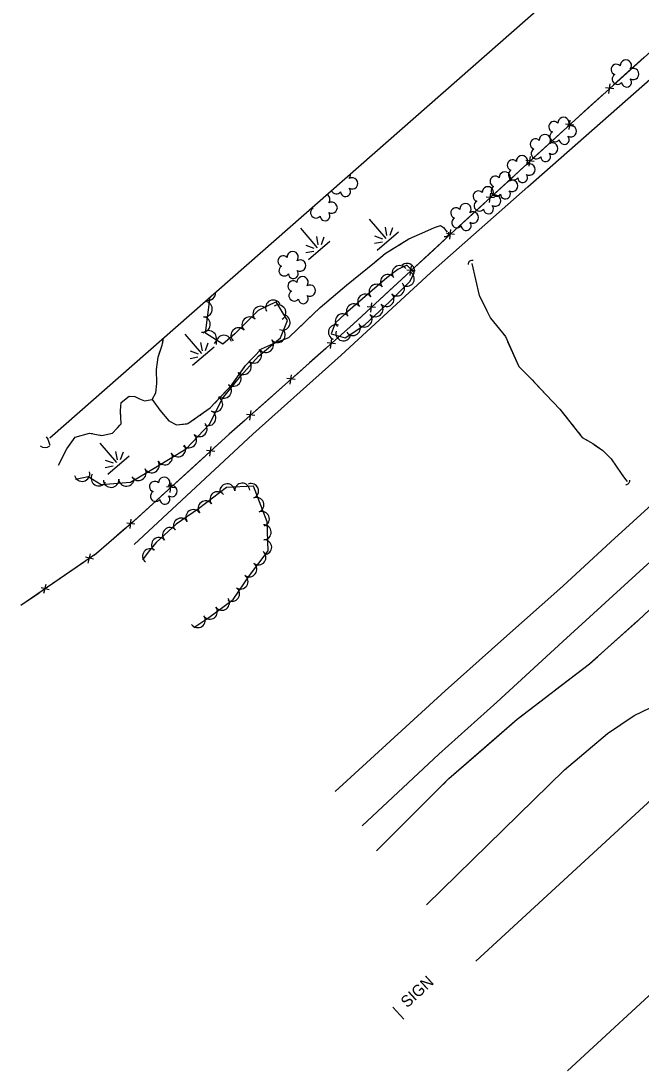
# Model space of a CAD drawing. Extents: x 295302 to 297577, y 27143 to 29590.
# Drawn here: x 295710 to 296036, y 28030 to 28582 of the extents above; entities that cross this region are included whole.
import ezdxf

# ---------------------------------------------------------------- set-up
doc = ezdxf.new("R2010")
doc.units = 0
for name, color, linetype in [('Level 11', 7, 'Continuous'), ('Level 12', 7, 'Continuous'), ('Level 14', 7, 'Continuous'), ('Level 15', 7, 'Continuous'), ('Level 17', 7, 'Continuous'), ('Level 18', 7, 'Continuous'), ('Level 19', 7, 'Continuous'), ('Level 4', 7, 'Continuous')]:
    doc.layers.add(name, color=color, linetype=linetype)

msp = doc.modelspace()

# ---------------------------------------------------------------- linework, layer by layer
at = {"layer": 'Level 11'}
for points in [[(295875.36, 28176.97), (295933.16, 28229.89), (295963.95, 28257.42), (295994.85, 28284.91), (296020.17, 28308.14), (296053.31, 28338.3), (296080.66, 28364.03), (296109.33, 28390.19), (296137.45, 28415.82), (296168.64, 28444.28), (296193.89, 28466.94), (296211.46, 28483.1), (296243.37, 28511.75), (296271.82, 28538.33), (296291, 28555.78), (296294.87, 28559.97), (296297.65, 28563.85)], [(295889.55, 28159.05), (295929.9, 28196.61), (295960.23, 28223.99), (295994.84, 28255.85), (296037.19, 28294.52), (296061.88, 28316.46), (296091.53, 28343.54), (296125.49, 28375.06), (296156.05, 28402.79), (296185.39, 28429.34), (296231.09, 28471.28), (296271.66, 28507.98), (296280.16, 28516.21), (296284, 28519.76), (296286.47, 28521.53), (296289.27, 28523.36), (296290.75, 28524.15), (296293.46, 28524.51), (296295.97, 28523.95)]]:
    msp.add_lwpolyline(points, dxfattribs=at)
at = {"layer": 'Level 12'}
msp.add_lwpolyline([(295997.3, 28030.32), (296109.73, 28134.03), (296059.4, 28189.22), (295949.16, 28088.06)], dxfattribs=at)
at = {"layer": 'Level 14'}
msp.add_line((295905.59, 28063.79), (295911.52, 28057.47), dxfattribs=at)
at = {"layer": 'Level 15'}
for p, q in [((296019.55, 28548.5), (296018.96, 28543.53)), ((296021.63, 28545.95), (296017.36, 28546.43)), ((296000.67, 28526.93), (295996.4, 28527.38)), ((295998.57, 28529.47), (295998.02, 28524.49)), ((295977.72, 28510.33), (295977.16, 28505.35)), ((295979.82, 28507.78), (295975.54, 28508.24)), ((295958.96, 28488.64), (295954.69, 28489.09)), ((295956.86, 28491.18), (295956.31, 28486.2)), ((295936.01, 28472.03), (295935.47, 28467.05)), ((295938.12, 28469.49), (295933.84, 28469.93)), ((295917.32, 28450.29), (295913.04, 28450.73)), ((295915.21, 28452.82), (295914.67, 28447.84)), ((295896.52, 28431.08), (295892.24, 28431.52)), ((295894.41, 28433.62), (295893.87, 28428.64)), ((295875.52, 28412.05), (295871.26, 28412.58)), ((295873.46, 28414.63), (295872.82, 28409.66)), ((295854.35, 28393.25), (295850.09, 28393.78)), ((295852.3, 28395.83), (295851.66, 28390.86)), ((295831.13, 28377.03), (295830.49, 28372.06)), ((295833.19, 28374.45), (295828.92, 28374.97)), ((295812.13, 28355.56), (295807.86, 28356.03)), ((295810.04, 28358.11), (295809.47, 28353.13)), ((295789.11, 28339.05), (295788.53, 28334.08)), ((295791.19, 28336.5), (295786.92, 28336.97)), ((295770.23, 28317.43), (295765.97, 28317.99)), ((295768.19, 28320.03), (295767.51, 28315.06)), ((295748.55, 28298.98), (295744.39, 28300.03)), ((295746.83, 28301.79), (295745.58, 28296.94)), ((295725.2, 28282.98), (295721.03, 28284.03)), ((295723.48, 28285.79), (295722.22, 28280.94))]:
    msp.add_line(p, q, dxfattribs=at)
for points in [[(296276.18, 28846.07), (296285.34, 28791.28), (296208.62, 28719.5), (296139.52, 28656.15), (296075.6, 28596.91), (296001.45, 28529.71), (295938.47, 28471.89), (295884.83, 28422.36), (295819.8, 28364.6), (295769.53, 28318.85), (295750.14, 28301.92), (295710.44, 28274.72)], [(296037.63, 28562.5), (296029.11, 28554.78)], [(296029.11, 28554.78), (296021.61, 28547.98)], [(296016.65, 28543.49), (296008.13, 28535.77)], [(296008.13, 28535.77), (296001.45, 28529.71), (296000.64, 28528.97)], [(295995.71, 28524.44), (295987.23, 28516.67)], [(295987.23, 28516.67), (295979.78, 28509.82)], [(295974.85, 28505.3), (295966.38, 28497.52)], [(295966.38, 28497.52), (295958.93, 28490.68)], [(295954, 28486.15), (295945.53, 28478.37)], [(295945.53, 28478.37), (295938.47, 28471.89), (295938.08, 28471.53)], [(295933.16, 28466.99), (295924.71, 28459.19)], [(295924.71, 28459.19), (295917.28, 28452.32)], [(295912.36, 28447.79), (295903.91, 28439.98)], [(295903.91, 28439.98), (295896.48, 28433.12)], [(295891.56, 28428.58), (295884.83, 28422.36), (295883.08, 28420.81)], [(295883.08, 28420.81), (295875.52, 28414.09)], [(295870.52, 28409.65), (295861.92, 28402.01)], [(295861.92, 28402.01), (295854.35, 28395.29)], [(295849.35, 28390.85), (295840.75, 28383.21)], [(295840.75, 28383.21), (295833.19, 28376.49)], [(295828.18, 28372.05), (295819.8, 28364.6), (295819.59, 28364.4)], [(295819.59, 28364.4), (295812.1, 28357.6)], [(295807.16, 28353.09), (295798.65, 28345.35)], [(295798.65, 28345.35), (295791.17, 28338.54)], [(295786.22, 28334.04), (295777.71, 28326.3)], [(295777.71, 28326.3), (295770.23, 28319.49)], [(295765.21, 28315.07), (295756.54, 28307.5)], [(295756.54, 28307.5), (295750.14, 28301.92), (295748.8, 28301)], [(295743.29, 28297.22), (295733.8, 28290.72)], [(295733.8, 28290.72), (295725.45, 28285)], [(295719.93, 28281.22), (295710.44, 28274.72)]]:
    msp.add_lwpolyline(points, dxfattribs=at)
for centre, radius, start, end in [((295933.03, 28470.48), 2.14, 259.782, 6.0216), ((295947.33, 28453.7), 2.17, 74.4067, 180.6463), ((296028.21, 28340.07), 1.84, 265.0937, 11.3332)]:
    msp.add_arc(centre, radius, start, end, dxfattribs=at)
at = {"layer": 'Level 17'}
for points in [[(295769.8, 28306.78), (295832.14, 28364.62), (295878.58, 28406.02), (295925.45, 28449.27), (295976.52, 28494.41), (296049.61, 28558.68), (296125.2, 28629.4), (296196.94, 28696.67), (296248.89, 28742.92), (296276.75, 28769.94), (296287.3, 28777.73)], [(295923.43, 28117.62), (295995.81, 28188.42), (296018.45, 28207.44), (296032.34, 28216.99), (296045.11, 28223.03)]]:
    msp.add_lwpolyline(points, dxfattribs=at)
at = {"layer": 'Level 18'}
for points in [[(295880.85, 28428.06), (295875.46, 28422.94), (295873.23, 28417.24), (295880.72, 28415.12), (295890.92, 28422.1), (295903.84, 28434.17), (295914.72, 28445.03), (295916.85, 28449.41), (295913.04, 28453.42), (295908.28, 28451.02), (295902.53, 28446.77), (295880.85, 28428.06)], [(295739.05, 28340.93), (295745.68, 28342.45), (295752.59, 28338.23), (295767.9, 28339.37), (295781.26, 28347.26), (295797.18, 28356.95), (295809.57, 28370.04), (295816.05, 28383.15), (295825.79, 28395.18), (295835.17, 28405.56), (295846.73, 28415.28), (295850.42, 28424.32), (295844.47, 28434.08), (295835.04, 28429.52), (295822.67, 28417.37), (295816.42, 28411.88), (295807.31, 28417.71), (295809.85, 28436.64)], [(295723.67, 28363.18), (295724.61, 28361.95), (295725.54, 28358.93)], [(295801.17, 28263.08), (295809.07, 28268.47), (295821.79, 28277.88), (295830.42, 28290.42), (295840.26, 28303.3), (295839.7, 28318.62), (295832.45, 28337.3), (295818.26, 28336.69), (295803.72, 28325.49), (295791.88, 28317.39), (295781.41, 28307.83), (295777.72, 28303.3), (295774.18, 28298.73)]]:
    msp.add_lwpolyline(points, dxfattribs=at)
for centre, radius, start, end in [((296023.07, 28556.05), 2.78, 43.9105, 251.6835), ((296028.04, 28558.09), 2.97, 320.9396, 182.1735), ((296023.61, 28551.02), 2.78, 120.5875, 321.5986), ((296031.92, 28553.7), 2.97, 238.5904, 121.5637), ((296028.4, 28549.44), 2.61, 183.2957, 41.2283), ((295995.3, 28528), 2.97, 320.9396, 182.1735), ((295990.33, 28525.96), 2.78, 43.9105, 251.6835), ((295999.18, 28523.61), 2.97, 238.5904, 121.5637), ((295980.57, 28516.95), 2.78, 43.9105, 251.6835), ((295985.54, 28518.99), 2.97, 320.9396, 182.1735), ((295990.87, 28520.93), 2.78, 120.5875, 321.5986), ((295995.66, 28519.35), 2.61, 183.2957, 41.2283), ((295981.11, 28511.92), 2.78, 120.5875, 321.5986), ((295989.41, 28514.6), 2.97, 238.5904, 121.5637), ((295968.52, 28505.88), 2.78, 43.9105, 251.6835), ((295973.49, 28507.92), 2.97, 320.9396, 182.1735), ((295985.9, 28510.34), 2.61, 183.2957, 41.2283), ((295969.07, 28500.85), 2.78, 120.5875, 321.5986), ((295977.37, 28503.53), 2.97, 238.5904, 121.5637), ((295880.46, 28500.66), 2.97, 320.9396, 10.6659), ((295884.33, 28496.27), 2.97, 238.5904, 121.5637), ((295959.47, 28497.31), 2.78, 43.9105, 251.6835), ((295964.44, 28499.35), 2.97, 320.9396, 182.1735), ((295968.32, 28494.96), 2.97, 238.5904, 121.5637), ((295973.85, 28499.27), 2.61, 183.2957, 41.2283), ((295876.03, 28493.58), 2.78, 202.9151, 321.5986), ((295880.82, 28492.01), 2.61, 183.2957, 41.2283), ((295950.56, 28489.54), 2.78, 43.9105, 251.6835), ((295955.53, 28491.58), 2.97, 320.9396, 182.1735), ((295960.01, 28492.28), 2.78, 120.5875, 321.5986), ((295964.8, 28490.7), 2.61, 183.2957, 41.2283), ((295869.69, 28487.91), 2.97, 320.9396, 60.0715), ((295951.1, 28484.51), 2.78, 120.5875, 321.5986), ((295959.4, 28487.19), 2.97, 238.5904, 121.5637), ((295865.26, 28480.84), 2.78, 120.5875, 321.5986), ((295864.72, 28485.87), 2.78, 237.8252, 251.6835), ((295873.56, 28483.52), 2.97, 238.5904, 121.5637), ((295938.88, 28480.72), 2.78, 43.9105, 251.6835), ((295943.85, 28482.76), 2.97, 320.9396, 182.1735), ((295947.72, 28478.37), 2.97, 238.5904, 121.5637), ((295955.89, 28482.93), 2.61, 183.2957, 41.2283), ((295870.05, 28479.26), 2.61, 183.2957, 41.2283), ((295939.42, 28475.69), 2.78, 120.5875, 321.5986), ((295944.21, 28474.11), 2.61, 183.2957, 41.2283), ((295853.08, 28457.53), 2.97, 320.9396, 182.1735), ((295848.11, 28455.49), 2.78, 43.9105, 251.6835), ((295856.95, 28453.14), 2.97, 238.5904, 121.5637), ((295913.09, 28450.37), 3.94, 313.5122, 133.4969), ((295848.65, 28450.46), 2.78, 120.5875, 321.5986), ((295853.44, 28448.88), 2.61, 183.2957, 41.2283), ((295903.09, 28444.53), 3.94, 40.8034, 220.7881), ((295909.26, 28449.18), 3.94, 36.496, 216.4806), ((295912.98, 28446.18), 3.94, 244.011, 63.9957), ((295853.33, 28442.34), 2.78, 43.9105, 251.6835), ((295858.3, 28444.38), 2.97, 320.9396, 182.1735), ((295862.17, 28439.99), 2.97, 238.5904, 121.5637), ((295897.12, 28439.37), 3.94, 40.8034, 220.7881), ((295907.87, 28441.11), 3.94, 224.976, 44.9607), ((295808.65, 28438.86), 4.04, 258.6125, 3.9518), ((295853.87, 28437.31), 2.78, 120.5875, 321.5986), ((295858.66, 28435.73), 2.61, 183.2957, 41.2283), ((295891.16, 28434.22), 3.94, 40.8034, 220.7881), ((295902.34, 28435.59), 3.94, 223.0574, 43.042), ((295806.86, 28430.24), 4.04, 262.3925, 82.3771), ((295836.26, 28427.76), 4.04, 44.4913, 224.476), ((295842.9, 28430.98), 4.04, 25.8364, 205.8211), ((295845.43, 28428.45), 4.04, 301.3712, 121.3558), ((295885.19, 28429.07), 3.94, 40.8034, 220.7881), ((295896.58, 28430.21), 3.94, 223.0574, 43.042), ((295805.79, 28422.24), 4.04, 262.3925, 82.3771), ((295830.5, 28422.1), 4.04, 44.4913, 224.476), ((295847.72, 28423.31), 4.04, 247.8139, 67.7986), ((295879.41, 28423.85), 3.94, 43.4922, 223.4769), ((295890.81, 28424.82), 3.94, 223.0574, 43.042), ((295824.73, 28416.44), 4.04, 44.4913, 224.476), ((295875.79, 28418.1), 3.94, 68.6685, 248.6532), ((295884.72, 28420.36), 3.94, 214.3884, 34.3731), ((295809.04, 28414.93), 4.04, 317.3999, 137.3845), ((295816.94, 28412.48), 4.04, 11.283, 191.2677), ((295845.16, 28416.73), 4.04, 220.0634, 40.048), ((295879.72, 28417.55), 3.94, 164.1978, 344.1825), ((295838.98, 28411.53), 4.04, 220.0634, 40.048), ((295832.71, 28406), 4.04, 227.9176, 47.9023), ((295827.3, 28400.01), 4.04, 227.9176, 47.9023), ((295821.95, 28393.8), 4.04, 231.0089, 50.9935), ((295816.87, 28387.53), 4.04, 231.0089, 50.9935), ((295812.31, 28380.36), 4.04, 243.7036, 63.6883), ((295808.73, 28373.12), 4.04, 243.7036, 63.6883), ((295804.12, 28367.36), 4.04, 226.5815, 46.5661), ((295798.57, 28361.5), 4.04, 226.5815, 46.5661), ((295723.08, 28361.76), 4.15, 233.0815, 307.3926), ((295785.92, 28352.57), 4.04, 211.3351, 31.3198), ((295792.82, 28356.77), 4.04, 211.3351, 31.3198), ((295779.03, 28348.4), 4.04, 210.5749, 30.5596), ((295742.52, 28343.89), 4.04, 192.8773, 12.8619), ((295751.32, 28341.48), 4.04, 148.5982, 328.5829), ((295772.08, 28344.29), 4.04, 210.5749, 30.5596), ((295757.72, 28340.73), 4.04, 184.2664, 4.2511), ((295765.77, 28341.33), 4.04, 184.2664, 4.2511), ((295780.68, 28337.09), 2.78, 43.9105, 251.6835), ((295785.65, 28339.13), 2.97, 320.9396, 182.1735), ((295789.52, 28334.74), 2.97, 238.5904, 121.5637), ((295818.74, 28334.65), 3.93, 2.4567, 182.4414), ((295826.58, 28334.99), 3.93, 2.4567, 182.4414), ((295831.22, 28334.79), 3.93, 291.2254, 111.2101), ((295781.22, 28332.06), 2.78, 120.5875, 321.5986), ((295786.01, 28330.48), 2.61, 183.2957, 41.2283), ((295813.6, 28330.51), 3.93, 37.6023, 217.587), ((295807.38, 28325.72), 3.93, 37.6023, 217.587), ((295834.06, 28327.47), 3.93, 291.2254, 111.2101), ((295800.91, 28321.08), 3.93, 34.3859, 214.3706), ((295836.9, 28320.15), 3.93, 291.2254, 111.2101), ((295794.43, 28316.64), 3.93, 34.3859, 214.3706), ((295837.85, 28313.14), 3.93, 272.0936, 92.0783), ((295782.91, 28306.42), 3.93, 42.4074, 222.3921), ((295788.71, 28311.71), 3.93, 42.4074, 222.3921), ((295838.13, 28305.29), 3.93, 272.0936, 92.0783), ((295778.21, 28300.58), 3.93, 52.204, 232.1886), ((295835.12, 28299.95), 3.93, 232.6236, 52.6083), ((295830.35, 28293.71), 3.93, 232.6236, 52.6083), ((295825.74, 28287.24), 3.93, 235.4641, 55.4487), ((295821.28, 28280.77), 3.93, 235.4641, 55.4487), ((295815.94, 28276.11), 3.93, 216.5046, 36.4893), ((295809.63, 28271.44), 3.93, 216.5046, 36.4893), ((295803.26, 28266.99), 3.93, 214.318, 34.3026)]:
    msp.add_arc(centre, radius, start, end, dxfattribs=at)
at = {"layer": 'Level 19'}
for p, q in [((295893.27, 28477.57), (295901.99, 28467.37)), ((295857.24, 28472.69), (295865.96, 28462.49)), ((295897.42, 28461.29), (295908.67, 28470.9)), ((295902.58, 28468.88), (295901.75, 28473.24)), ((295905.47, 28472.87), (295904.02, 28468.89)), ((295861.39, 28456.41), (295872.63, 28466.02)), ((295866.54, 28464), (295865.72, 28468.36)), ((295869.43, 28467.99), (295867.99, 28464.01)), ((295896.06, 28464.83), (295900.22, 28465.64)), ((295900.45, 28467.06), (295896.27, 28468.56)), ((295860.03, 28459.95), (295864.18, 28460.76)), ((295864.41, 28462.18), (295860.24, 28463.68)), ((295796.41, 28417.13), (295805.13, 28406.93)), ((295800.55, 28400.85), (295811.8, 28410.47)), ((295805.71, 28408.44), (295804.88, 28412.8)), ((295808.6, 28412.43), (295807.16, 28408.45)), ((295799.19, 28404.39), (295803.35, 28405.2)), ((295803.58, 28406.62), (295799.41, 28408.12)), ((295751.84, 28359.9), (295760.56, 28349.7)), ((295761.15, 28351.22), (295760.32, 28355.57)), ((295764.04, 28355.2), (295762.59, 28351.22)), ((295759.02, 28349.39), (295754.84, 28350.89)), ((295755.99, 28343.62), (295767.24, 28353.24)), ((295754.63, 28347.16), (295758.79, 28347.97))]:
    msp.add_line(p, q, dxfattribs=at)
for points in [[(295779.27, 28382.85), (295783.28, 28377.18), (295788.01, 28371.59), (295792.12, 28369.59), (295797.97, 28370.15), (295809.82, 28378.42), (295821.06, 28390.45), (295828.25, 28400.6), (295836.67, 28409.42), (295843.1, 28412.25), (295851.08, 28415.44), (295860, 28423.9), (295867.47, 28431.04), (295881.41, 28442.78), (295896.08, 28454.72), (295901.61, 28459.53), (295914.04, 28467.12), (295922.45, 28470.89), (295927.62, 28473.2), (295930.77, 28474.16), (295932.24, 28473.11), (295934.21, 28470.74)], [(295913.04, 28466.51), (295914.04, 28467.12), (295922.45, 28470.89), (295927.62, 28473.2), (295930.77, 28474.16), (295932.24, 28473.11), (295934.21, 28470.74)], [(295908.76, 28463.9), (295910.19, 28464.77)], [(295900.36, 28458.44), (295901.61, 28459.53), (295901.62, 28459.54)], [(295904.48, 28461.28), (295905.91, 28462.15)], [(295879.12, 28440.85), (295881.41, 28442.78), (295896.08, 28454.72), (295897.84, 28456.25)], [(295947.18, 28454.21), (295951, 28437.51), (295956.89, 28425.6), (295964.74, 28415.93), (295971.86, 28400.1), (295978.82, 28393.08), (295986.17, 28385.25), (295993.4, 28377.76), (296005.15, 28362.95), (296010.62, 28359.67), (296015.95, 28356.1), (296020.27, 28351.7), (296025.51, 28344.06), (296027.34, 28341.5), (296028.71, 28339.72)], [(295947.18, 28454.21), (295951, 28437.51), (295954.96, 28429.51)], [(295860.95, 28424.81), (295867.47, 28431.04), (295879.12, 28440.85)], [(295956.55, 28426.28), (295956.89, 28425.6), (295957.54, 28424.8)], [(295857.32, 28421.36), (295858.53, 28422.51)], [(295959.81, 28422.01), (295960.94, 28420.61)], [(295730.22, 28348.38), (295734.51, 28356.93), (295738.95, 28363.09), (295746.46, 28365.22), (295752.92, 28363.95), (295758.49, 28365.12), (295763.04, 28370.04), (295762.6, 28377.08), (295763.05, 28381.28), (295767.15, 28384.63), (295770.17, 28384.35), (295772.63, 28383.14), (295775.29, 28382.1), (295779.27, 28382.85), (295781.27, 28386.26), (295781.75, 28391.3), (295781.61, 28398.59), (295782.44, 28405.03), (295784.55, 28411.36), (295785.27, 28415.07)], [(295849.75, 28414.91), (295851.08, 28415.44), (295851.25, 28415.6)], [(295853.68, 28417.9), (295854.89, 28419.06)], [(295963.21, 28417.82), (295964.34, 28416.42)], [(295784.66, 28411.93), (295785.01, 28413.72)], [(295827.55, 28399.62), (295828.25, 28400.6), (295836.67, 28409.42), (295843.1, 28412.25), (295846.64, 28413.67)], [(295965.96, 28413.23), (295971.86, 28400.1), (295978.82, 28393.08), (295980.04, 28391.78)], [(295779.18, 28382.83), (295779.27, 28382.85), (295781.27, 28386.26), (295781.75, 28391.3), (295781.61, 28398.59), (295782.44, 28405.03), (295783.58, 28408.44)], [(295812.18, 28380.95), (295821.06, 28390.45), (295827.55, 28399.62)], [(295980.04, 28391.78), (295986.17, 28385.25), (295993.4, 28377.76), (295997.56, 28372.52)], [(295762.87, 28372.69), (295762.6, 28377.08), (295763.05, 28381.28), (295767.15, 28384.63), (295770.17, 28384.35), (295772.63, 28383.14), (295775.29, 28382.1), (295779.18, 28382.83)], [(295779.27, 28382.85), (295783.28, 28377.18), (295788.01, 28371.59), (295792.12, 28369.59), (295797.5, 28370.11)], [(295808.55, 28377.53), (295809.82, 28378.42), (295809.9, 28378.51)], [(295800.32, 28371.79), (295801.69, 28372.75)], [(295804.43, 28374.66), (295805.81, 28375.62)], [(295756.92, 28364.79), (295758.49, 28365.12), (295758.64, 28365.28)], [(295761.12, 28367.97), (295762.36, 28369.31)], [(295999.79, 28369.7), (296000.91, 28368.29)], [(296003.14, 28365.48), (296004.26, 28364.07)], [(295730.22, 28348.38), (295734.51, 28356.93), (295738.95, 28363.09), (295746.46, 28365.22), (295747.96, 28364.93)], [(295751.55, 28364.22), (295752.92, 28363.95), (295753.34, 28364.04)], [(296007.01, 28361.83), (296008.55, 28360.91)], [(296011.6, 28359.01), (296015.95, 28356.1), (296020.27, 28351.7), (296025.51, 28344.06), (296027.34, 28341.5), (296028.71, 28339.72)], [(295897.02, 28145.94), (295935.14, 28183.88), (295971, 28214.98), (296008.91, 28244.12), (296034.43, 28266.81), (296058.6, 28289.49), (296067.61, 28298.02), (296065.26, 28300.62)], [(296013.24, 28247.97), (296034.21, 28266.61)], [(295991.25, 28230.54), (296008.91, 28244.12), (296013.24, 28247.97)], [(295986.65, 28227.01), (295988.18, 28228.19)], [(295982.04, 28223.47), (295983.58, 28224.65)], [(295953.01, 28199.37), (295971, 28214.98), (295974.37, 28217.57)], [(295977.44, 28219.93), (295978.97, 28221.11)], [(295932.01, 28180.76), (295935.14, 28183.88), (295953.01, 28199.37)], [(295927.89, 28176.67), (295929.26, 28178.03)], [(295923.78, 28172.57), (295925.15, 28173.94)], [(295919.66, 28168.47), (295921.03, 28169.84)], [(295897.02, 28145.94), (295916.92, 28165.74)]]:
    msp.add_lwpolyline(points, dxfattribs=at)
at = {"layer": 'Level 4'}
msp.add_lwpolyline([(295725.55, 28362.64), (296492.89, 29036.34)], dxfattribs=at)

# ---------------------------------------------------------------- texts
at = {"layer": 'Level 14'}
msp.add_text('SIGN', height=6, rotation=42.516, dxfattribs=at).set_placement((295913.18, 28063.16))

doc.saveas('drawing.dxf')
